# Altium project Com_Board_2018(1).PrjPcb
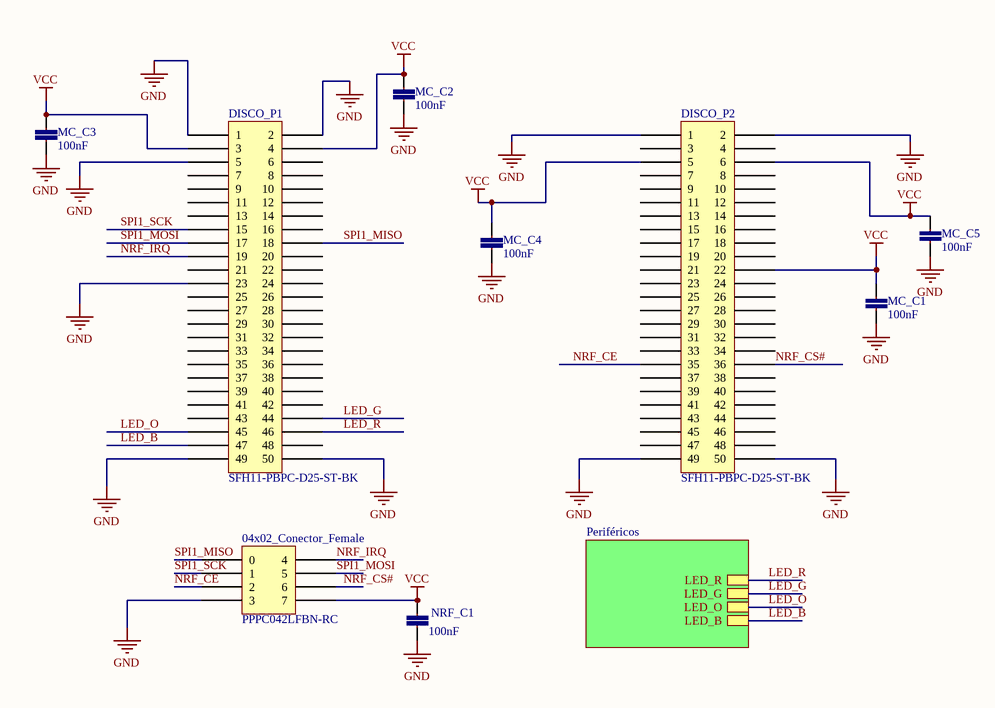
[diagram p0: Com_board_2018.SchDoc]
2 sheets, 25 parts. Net scope: hierarchical (ports join the sheet entries above them; power ports are global).
Board file: Com_Board_2018.PcbDoc
Sheets:
  Com_board_2018.SchDoc
    Periféricos = Periféricos.SchDoc

## Sheet Com_board_2018.SchDoc
size A4

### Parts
04x02_Conector_Female  PPPC042LFBN-RC  [04x02_Conector_Female]
DISCO_P1  SFH11-PBPC-D25-ST-BK  [25x02_Conector_Female]
DISCO_P2  SFH11-PBPC-D25-ST-BK  [25x02_Conector_Female]
MC_C1  100nF  [0402-CAP]
MC_C2  100nF  [0402-CAP]
MC_C3  100nF  [0402-CAP]
MC_C4  100nF  [0402-CAP]
MC_C5  100nF  [0402-CAP]
NRF_C1  100nF  [0402-CAP]

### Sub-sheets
Periféricos = Periféricos.SchDoc: LED_R, LED_G, LED_O, LED_B

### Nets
GND: 04x02_Conector_Female.3 DISCO_P1.1 DISCO_P1.2 DISCO_P1.5 DISCO_P1.23 DISCO_P1.49 DISCO_P1.50 DISCO_P2.1 DISCO_P2.2 DISCO_P2.49 DISCO_P2.50 MC_C1.1 MC_C2.1 MC_C3.2 MC_C4.1 MC_C5.1 NRF_C1.2
VCC: 04x02_Conector_Female.7 DISCO_P1.3 DISCO_P1.4 DISCO_P2.5 DISCO_P2.6 DISCO_P2.22 MC_C1.2 MC_C2.2 MC_C3.1 MC_C4.2 MC_C5.2 NRF_C1.1
LED_B: DISCO_P1.47 ; sheet Periféricos/LED_B  [project net Blue_led]
LED_G: DISCO_P1.44 ; sheet Periféricos/LED_G
LED_O: DISCO_P1.45 ; sheet Periféricos/LED_O
LED_R: DISCO_P1.46 ; sheet Periféricos/LED_R
NRF_CE: 04x02_Conector_Female.2 DISCO_P2.35
NRF_CS#: 04x02_Conector_Female.6 DISCO_P2.36
NRF_IRQ: 04x02_Conector_Female.4 DISCO_P1.19
SPI1_MISO: 04x02_Conector_Female.0 DISCO_P1.18
SPI1_MOSI: 04x02_Conector_Female.5 DISCO_P1.17
SPI1_SCK: 04x02_Conector_Female.1 DISCO_P1.15

Not connected (* = marked no-connect by the designer): DISCO_P1 6 7 8 9 10 11 12 13 14 16 20 21 22 24 25 26 27 28 29 30 31 32 33 34 35 36 37 38 39 40 41 42 43 48; DISCO_P2 3 4 7 8 9 10 11 12 13 14 15 16 17 18 19 20 21 23 24 25 26 27 28 29 30 31 32 33 34 37 38 39 40 41 42 43 44 45 46 47 48

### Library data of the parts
04x02_Conector_Female = 04x02_Conector_Female: 8 Position Header Connector 0.100" (2.54mm) Through Hole Gold
DISCO_P1 DISCO_P2 = 25x02_Conector_Female: 50 Position Header Connector 0.100" (2.54mm) Through Hole Gold
MC_C1-MC_C5 NRF_C1 = CC0402-100nF-A.12: CAP CER 0.1UF 10V 20% X5R 0402; Part No: VJ0402V104ZXQPBC; Cod EMS: 05.281.006.133; Value: 100n

## Sheet Periféricos.SchDoc
size A4
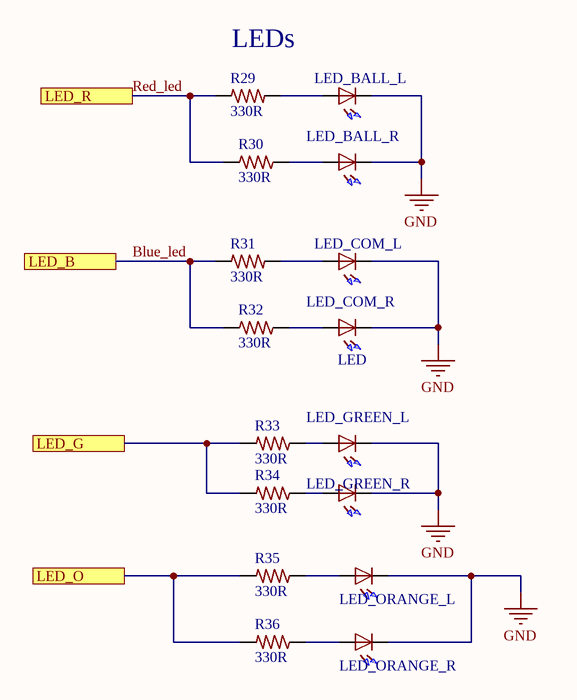
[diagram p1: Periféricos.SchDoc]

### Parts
LED_BALL_L  LED  [LED-5MM-PCB]  (value not drawn)
LED_BALL_R  LED  [LED-5MM-PCB]  (value not drawn)
LED_COM_L  LED  [LED-5MM-PCB]  (value not drawn)
LED_COM_R  LED  [LED-5MM-PCB]
LED_GREEN_L  LED  [LED-5MM-PCB]  (value not drawn)
LED_GREEN_R  LED  [LED-5MM-PCB]  (value not drawn)
LED_ORANGE_L  LED  [LED-5MM-PCB]  (value not drawn)
LED_ORANGE_R  LED  [LED-5MM-PCB]  (value not drawn)
R29  330R  [0402-RES-HD]
R30  330R  [0402-RES-HD]
R31  330R  [0402-RES-HD]
R32  330R  [0402-RES-HD]
R33  330R  [0402-RES-HD]
R34  330R  [0402-RES-HD]
R35  330R  [0402-RES-HD]
R36  330R  [0402-RES-HD]

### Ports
LED_B, LED_G, LED_O, LED_R

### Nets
GND: LED_BALL_L.1(K) LED_BALL_R.1(K) LED_COM_L.1(K) LED_COM_R.1(K) LED_GREEN_L.1(K) LED_GREEN_R.1(K) LED_ORANGE_L.1(K) LED_ORANGE_R.1(K)
Blue_led: R31.1 R32.1 ; port LED_B
LED_G: R33.1 R34.1 ; port LED_G
LED_O: R35.1 R36.1 ; port LED_O
Red_led: R29.1 R30.1 ; port LED_R  [project net LED_R]
NetLED_BALL_L_2: LED_BALL_L.2(A) R29.2
NetLED_BALL_R_2: LED_BALL_R.2(A) R30.2
NetLED_COM_L_2: LED_COM_L.2(A) R31.2
NetLED_COM_R_2: LED_COM_R.2(A) R32.2
NetLED_GREEN_L_2: LED_GREEN_L.2(A) R33.2
NetLED_GREEN_R_2: LED_GREEN_R.2(A) R34.2
NetLED_ORANGE_L_2: LED_ORANGE_L.2(A) R35.2
NetLED_ORANGE_R_2: LED_ORANGE_R.2(A) R36.2

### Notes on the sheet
- (near R29) LEDs

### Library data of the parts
LED_BALL_L LED_BALL_R LED_COM_L LED_COM_R LED_GREEN_L LED_GREEN_R LED_ORANGE_L LED_ORANGE_R = LED-5MM-3: LED 5MM PTH
R29-R36 = R0402-330R-7: RES 330 OHM 1/10W 1% 0402 SMD; Part No: ERJ-2RKF3300X; Cod EMS: 05.280.029.506; Value: 330; Family Description: RESISTOR FILME ESPESSO 10R-1M / 1/10W / 1% / 0402. P/N: ERJ-2RKF....X – PANASONIC ELECTRONIC COMPONENTS.

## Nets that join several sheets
GND: Com_board_2018 (17 pins), Periféricos (8 pins)
Blue_led: Com_board_2018 (DISCO_P1.47), Periféricos (R31.1 R32.1)
LED_G: Com_board_2018 (DISCO_P1.44), Periféricos (R33.1 R34.1)
LED_O: Com_board_2018 (DISCO_P1.45), Periféricos (R35.1 R36.1)
LED_R: Com_board_2018 (DISCO_P1.46), Periféricos (R29.1 R30.1)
